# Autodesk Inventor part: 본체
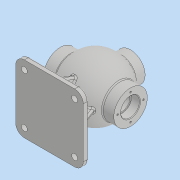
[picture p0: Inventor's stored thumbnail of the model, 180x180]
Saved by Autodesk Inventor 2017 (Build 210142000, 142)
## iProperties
Part Number: 본체
Material: 일반
Document SubType Name: Modeling
Designer: MRC
Density: 1 g/cm^3
Appearance: 기본값
Author: MRC
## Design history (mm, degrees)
sketch "스케치1"
  geometry: L1 (-65, 0)-(65, 0); L2 (65, 0)-(65, 31); L3 (65, 31)-(44.215, 31); L4 (-65, 0)-(-65, 31); L5 (-65, 31)-(-44.215, 31); A1 r 54 centre (0, 0) between (44.215, 31) and (-44.215, 31); A2 r 44 centre (0, 0) between (44, 0) and (-44, 0); 2 further points
  constraints: 10 end point, 4 point on circle, 3 coincident, 2 centre point, 2 horizontal, 2 vertical, 1 midpoint, 1 perpendicular
  dimensions: "d0" = 108 diameter of A1; "d1" = 88 diameter of A2; "d2" = 130 distance of L1.start L1.end; "d3" = 31 distance of L1.end L2.end; "d4" = 31 distance of L1.start L4.end
revolve "회전1" stored, may be unused: angle "d5" = 90 deg
sketch "스케치2"
  geometry: L1 (-44, 0)-(44, 0); A1 r 44 centre (0, 0) between (44, 0) and (-44, 0); 2 further points
  constraints: 2 end point, 2 point on circle, 1 centre point, 1 coincident, 1 horizontal, 1 midpoint
  dimensions: "d6" = 88 distance of L1.start L1.end; "d8" = 44 radius of A1
revolve "회전2" sketch "스케치2" stored, may be unused: angle "d9" = 90 deg
node "작업 평면1"
sketch "스케치3"
  geometry: C1 r 27 at (0, 0); 1 further point
  constraints: 1 centre point, 1 coincident
  dimensions: "d11" = 54 diameter of C1
extrude "돌출1" join sketch "스케치3" stored distance "d12" = 10; taper "d13" = 0 deg
hole "구멍1" diameter "d16" = 30; stored, may be unused: countersink angle "d20" = 90 deg, drill point angle "d22" = 0 deg; dims "d14" = 10, "d15" = 10, "d17" = 6, "d18" = 35, "d19" = 16, "d21" = 30
sketch "스케치4"
  geometry: C1 r 17.5 at (0, 0) reference; 1 further point
  constraints: 1 vertical alignment
  dimensions: "d23" = 24 distance of C1.centre point (0, 24)
hole "구멍2" sketch "스케치4" at (0, 24) diameter "d24" = 3.242; stored, may be unused: countersink angle "d28" = 90 deg, drill point angle "d30" = 118 deg; dims "d25" = 12, "d26" = 35, "d27" = 16, "d29" = 15
chamfer "모따기1" distance "d34" = 1; stored, may be unused: second distance "d35" = 2, angle "d36" = 45 deg
fillet "모깎기1" dims "d37" = 0.6
sketch "스케치5"
  geometry: C1 r 27 at (0, 0) reference; C2 r 13 at (0, 0)
  constraints: 1 centre point, 1 coincident
  dimensions: "d38" = 26 diameter of C2
extrude "돌출2" cut sketch "스케치5" distance "d39" = 25; taper "d40" = 0 deg
fillet "모깎기2" dims "d41" = 3
sketch "스케치6"
  geometry: C1 r 13 at (0, 0) reference; 1 further point
  constraints: 1 vertical alignment
  dimensions: "d42" = 20 distance of C1.centre point (0, -20)
hole "구멍3" sketch "스케치6" at (0, -20) diameter "d43" = 3.242; stored, may be unused: countersink angle "d47" = 90 deg, drill point angle "d49" = 118 deg; dims "d44" = 9, "d45" = 35, "d46" = 16, "d48" = 11
sketch "스케치7"
  geometry: L1 (-62.5, -75)-(62.5, -75); L2 (62.5, -75)-(62.5, -85); L3 (62.5, -85)-(-62.5, -85); L4 (-62.5, -85)-(-62.5, -75); 2 further points
  constraints: 8 end point, 2 parallel, 1 horizontal, 1 midpoint, 1 perpendicular, 1 vertical alignment
  dimensions: "d53" = 85 distance from line of L3 point (0, 0); "d54" = 10 distance of L1.end L2.end; "d55" = 125 distance of L2.end L3.end
extrude "돌출3" join sketch "스케치7" stored distance "d56" = 125; taper "d57" = 0 deg
fillet "모깎기3" dims "d58" = 16
fillet "모깎기4" dims "d59" = 16
sketch "스케치8"
  geometry: C1 r 5.5 at (0, 16); C2 r 5.5 at (0, 109); C3 r 5.5 at (93, 109); C4 r 5.5 at (93, 16); A1 r 16 centre (93, 109) between (109, 109) and (93, 125) reference; A2 r 16 centre (0, 109) between (0, 125) and (-16, 109) reference; A3 r 16 centre (0, 16) between (-16, 16) and (0, 0) reference; A4 r 16 centre (93, 16) between (93, 0) and (109, 16) reference; 1 further point
  constraints: 4 centre point, 4 coincident
  dimensions: "d60" = 11 diameter of C1; "d61" = 11 diameter of C2; "d62" = 11 diameter of C3; "d63" = 11 diameter of C4
extrude "돌출4" cut sketch "스케치8" distance "d64" = 125; taper "d65" = 0 deg
sketch "스케치10"
  geometry: L1 (93, 0)-(0, 0) reference; L2 (109, 16)-(109, 109) reference; L3 (42.5, 113)-(50.5, 113); L4 (50.5, 113)-(50.5, 12); L5 (50.5, 12)-(42.5, 12); L6 (42.5, 12)-(42.5, 113); L7 (42.5, 113)-(50.5, 12); L8 (50.5, 113)-(42.5, 12); L9 (-4, 66.5)-(97, 66.5); L10 (97, 66.5)-(97, 58.5); L11 (97, 58.5)-(-4, 58.5); L12 (-4, 58.5)-(-4, 66.5); L13 (-4, 66.5)-(97, 58.5); L14 (97, 66.5)-(-4, 58.5); 1 further point
  constraints: 24 end point, 4 midpoint, 4 parallel, 2 horizontal, 2 perpendicular
  dimensions: "d66" = 12 distance between parallel lines of L10 L2; "d67" = 12 distance between parallel lines of L1 L5; "d68" = 8 distance of L3.start L3.end; "d69" = 8 distance of L9.end L10.end
extrude "돌출5" join sketch "스케치10" stored distance "d70" = 125; taper "d71" = 0 deg
feature "면 기울기1" dims angle "d72" = 20 deg
fillet "모깎기5" dims "d73" = 3
fillet "모깎기6" dims "d74" = 3
node "작업 평면2"
sketch "스케치12"
  geometry: L1 (-27, 65)-(27, 65) reference; 2 further points
  constraints: 1 vertical alignment, 1 other
  dimensions: "d76" = 9 distance from line of L1 point (0, 56)
feature "엠보싱1" sketch "스케치12" dims "d1" = 88, "d77" = 0.5, "d78" = 0
chamfer "모따기2" distance "d79" = 1; stored, may be unused: second distance "d80" = 2, angle "d81" = 45 deg
fillet "모깎기7" dims "d82" = 0.6
chamfer "모따기3" distance "d83" = 1; stored, may be unused: second distance "d84" = 2, angle "d85" = 45 deg
node "솔리드1"
pattern_circular "원형 패턴1" dims angle "d32" = 360 deg
mirror "미러1"
pattern_circular "원형 패턴2" dims angle "d51" = 360 deg
other parameters: "d10" = 65
